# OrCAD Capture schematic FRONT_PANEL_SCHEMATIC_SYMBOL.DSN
size A
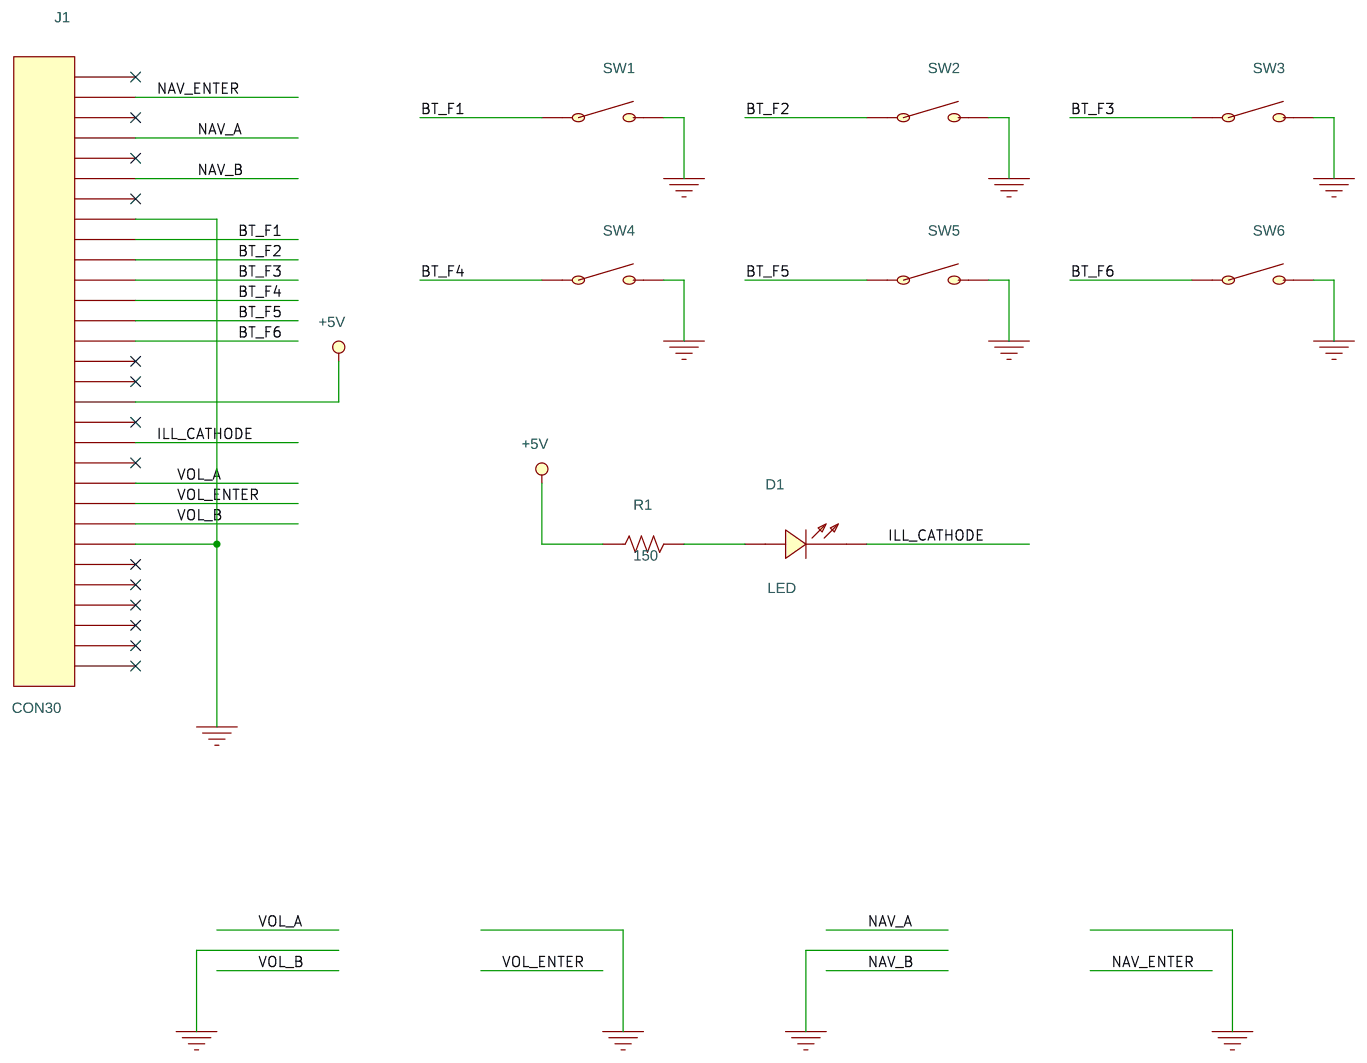
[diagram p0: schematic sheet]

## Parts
D1  LED
J1  CON30
R1  150  [AXRC05]
SW1  SW2  [SW_F160QG_EWI]
SW2  SW2  [SW_F160QG_EWI]
SW3  SW2  [SW_F160QG_EWI]
SW4  SW2  [SW_F160QG_EWI]
SW5  SW2  [SW_F160QG_EWI]
SW6  SW2  [SW_F160QG_EWI]

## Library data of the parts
D1 = LED
J1 = CON30
R1 = R
SW1-SW6 = TL1015AF160QG

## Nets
+5V: J1.17 R1.1
GND: J1.8 J1.24 SW1.2 SW2.2 SW3.2 SW4.2 SW5.2 SW6.2
BT_F1: J1.9 SW1.1
BT_F2: J1.10 SW2.1
BT_F3: J1.11 SW3.1
BT_F4: J1.12 SW4.1
BT_F5: J1.13 SW5.1
BT_F6: J1.14 SW6.1
ILL_CATHODE: D1.1(CATHODE) J1.19
NAV_A: J1.4
NAV_B: J1.6
NAV_ENTER: J1.2
VOL_A: J1.21
VOL_B: J1.23
VOL_ENTER: J1.22
N00512: D1.2(ANODE) R1.2

Not connected (* = marked no-connect by the designer): J1 1* 3* 5* 7* 15* 16* 18* 20* 25* 26* 27* 28* 29* 30*
